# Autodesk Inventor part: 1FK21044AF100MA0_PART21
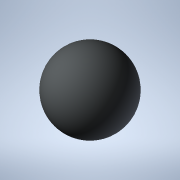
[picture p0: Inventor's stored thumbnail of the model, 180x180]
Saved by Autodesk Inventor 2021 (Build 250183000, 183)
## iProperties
Created: 2025-04
Part Number: 1FK21044AF100MA0_PART21
Material: Generic
Catalog Web Link: www.3dfindit.com
Description: -Servo synchronous motor
Document SubType Name: Modeling
Designer: psAdmin
Mass: 0.137258 g
Surface Area: 1.2868 cm^2
Volume: 0.137258 cm^3
Density: 1 g/cm^3
Appearance: PSOLRGB-212-217-219
Category: PARTsolutions
Title: 1FK21044AF100MA0_PART21
Author: Cadenas PARTsolutions
Comments: Servo synchronous motor
Sending System: PARTsolutions
Preprocessor: ST-DEVELOPER v19.3
PSOL_IDENT_0: {$CADENAS_DATA/23d-libs/siemens_ag/_cat_/ec/e4/1fk21044af100ma0.prj},216 {VTYP=3D},{NB=1FK21044AF100
PSOL_IDENT_1: MA0_PART21},{LINA=1FK21044AF100MA0_PART21},{NN=1FK21044AF100MA0_PART21},{NOPRJ=TRUE},{DATE=19.08.202
PSOL_IDENT_2: 5 14:01:05},{GEOMDATE=30.07.2025 02:01:01},{VERSION=},{LINEID=10},{WBVAR=},{WBNUMERIC=}  {NB=1FK2104
PSOL_IDENT_3: 4AF100MA0_PART21},{LINA=1FK21044AF100MA0_PART21},{KT=DUMMY},{PREVIEW=../../../_pool_/cb/72/p_d211_xx
PSOL_IDENT_4: _00434j.png},{DESCSHORT=SIMOTICS S-1FK2 HD, SINAMICS S210 3AC 400V-480V, 1.27 Nm, 3000 rpm},{DESCLON
PSOL_IDENT_5: G=SIMOTICS S-1FK2 HD servo motor M0=1.27 Nm; PN = 0.4 kW at nN=3000 rpm (380-480 V); PN = 0.2 kW at
PSOL_IDENT_6: nN=1500 rpm (200-240 V); with holding brake; degree of protection IP64; cylindrical shaft D19x40mm;
PSOL_IDENT_7: absolute encoder 22-bit + 12-bit multiturn (encoder AM22DQC); with OCC interface; plug size M17, rot
PSOL_IDENT_8: atable; SIMOTICS S-1FK2 servomotorfor a wide range of uses in industrial environments. SIMOTICS S‑1F
PSOL_IDENT_9: K2 servomotors are compact synchronous motors with a high dynamic performance that set themselves ap
PSOL_IDENT_10: art as a result of their high power density, degree of protection and overload capability. The motor
PSOL_IDENT_11: s are available in two variants: as High Dynamic variant (highest dynamic performance as a result of
PSOL_IDENT_12: the low intrinsic moment of inertia for applications demanding a high dynamic performance with low
PSOL_IDENT_13: moved masses) - and as Compact variant (precise and stable closed-loop control for medium up to larg
PSOL_IDENT_14: e moved masses as a result of a medium intrinsic moment of inertia). SIMOTICSS‑1FK2 servomotors full
PSOL_IDENT_15: y exploit their strengths in a system with the SINAMICSS210 frequency converter and simple connectio
PSOL_IDENT_16: n using the one cable connection (OCC). Advantages include the short control and positioning times,
PSOL_IDENT_17: fast and precise correction of disturbing quantities as well as stable control with a high dynamic p
PSOL_IDENT_18: erformance. The servo motors can be configured to address a wide range of requirements. For example
PSOL_IDENT_19: with and without holding brake, IP64 or IP65 degree of protection, singleturn or multiturn absolute
PSOL_IDENT_20: encoders - to name just a few. Further, the servomotors are available in different shaft heights ext
PSOL_IDENT_21: ending from 20 to 100. A shaft sealing ring is available to achieve an IP65 degree of protection and
PSOL_IDENT_22: for subsequent mounting at the motor or as spare part. SIMOTICS - the optimum motor for each and ev
PSOL_IDENT_23: ery motion control application.},{INTNO=195125043275},{SUPPLIERALTNO=1FK2104-4AF10-0MA0},{MANUID=1FK
PSOL_IDENT_24: 21044AF100MA0},{MANUNAME=Siemens},{MANUTYPEDESC=Synchronous motor 1FK2-HD 1.27 NM},{AAU732=SIMOTICS}
PSOL_IDENT_25: ,{AAO057=S-1FK2},{AAU734=SIMOTICS S-1FK2 HD servo motor M0=1.27 Nm; PN = 0.4 kW at nN=3000 rpm (380-
PSOL_IDENT_26: 480 V); PN = 0.2 kW at nN=1500 rpm (200-240 V); with holding brake; degree of protection IP64; cylin
PSOL_IDENT_27: drical shaft D19x40mm; absolute encoder 22-bit + 12-bit multiturn (encoder AM22DQC); with OCC interf
PSOL_IDENT_28: ace; plug size M17, rotatable;},{AAW338=Synchronous motor 1FK2-HD 1.27 NM},{AAO742=SIMOTICS},{AAO663=
PSOL_IDENT_29: 4042948694015},{NOCUPEROU=1},{PRICEQUANTITY=1},{QUANTITYMIN=1},{QUANTITYINT=1},{CTN=85015100},{COO=D
PSOL_IDENT_30: E},{AAO676=1FK2104-4AF10-0MA0},{AAO677=Siemens AG},{ORDERUNIT=C62},{CONTENTUNIT=C62}
NB: 1FK21044AF100MA0_PART21
NT: Servo synchronous motor
NBSYN: $MANUID._PART21
LINA: 1FK21044AF100MA0_PART21
CATALOG: SIEMENS
PREVIEW: ../../../_pool_/cb/72/p_d211_xx_00434j.png
DESCSHORT: SIMOTICS S-1FK2 HD, SINAMICS S210 3AC 400V-480V, 1.27 Nm, 3000 rpm
DESCLONG: SIMOTICS S-1FK2 HD servo motor M0=1.27 Nm; PN = 0.4 kW at nN=3000 rpm (380-480 V); PN = 0.2 kW at nN=1500 rpm (200-240 V); with holding brake; degree of protect
INTNO: 195125043275
SUPPLIERALTNO: 1FK2104-4AF10-0MA0
MANUID: 1FK21044AF100MA0
MANUNAME: Siemens
MANUTYPEDESC: Synchronous motor 1FK2-HD 1.27 NM
AAU732: SIMOTICS
AAO057: S-1FK2
AAU734: SIMOTICS S-1FK2 HD servo motor M0=1.27 Nm; PN = 0.4 kW at nN=3000 rpm (380-480 V); PN = 0.2 kW at nN=1500 rpm (200-240 V); with holding brake; degree of protect
AAW338: Synchronous motor 1FK2-HD 1.27 NM
AAO742: SIMOTICS
AAO663: 4042948694015.0
NOCUPEROU: 1
PRICEQUANTITY: 1
QUANTITYMIN: 1
QUANTITYINT: 1
CTN: 85015100
COO: DE
ARTICLENO: 1FK21044AF100MA0_PART21
BOMINFO: 1FK21044AF100MA0_PART21
CREATOR: CADENAS GmbH
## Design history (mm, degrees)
feature "2025_04_17_15_33_01_0673"
body "Solid1"
